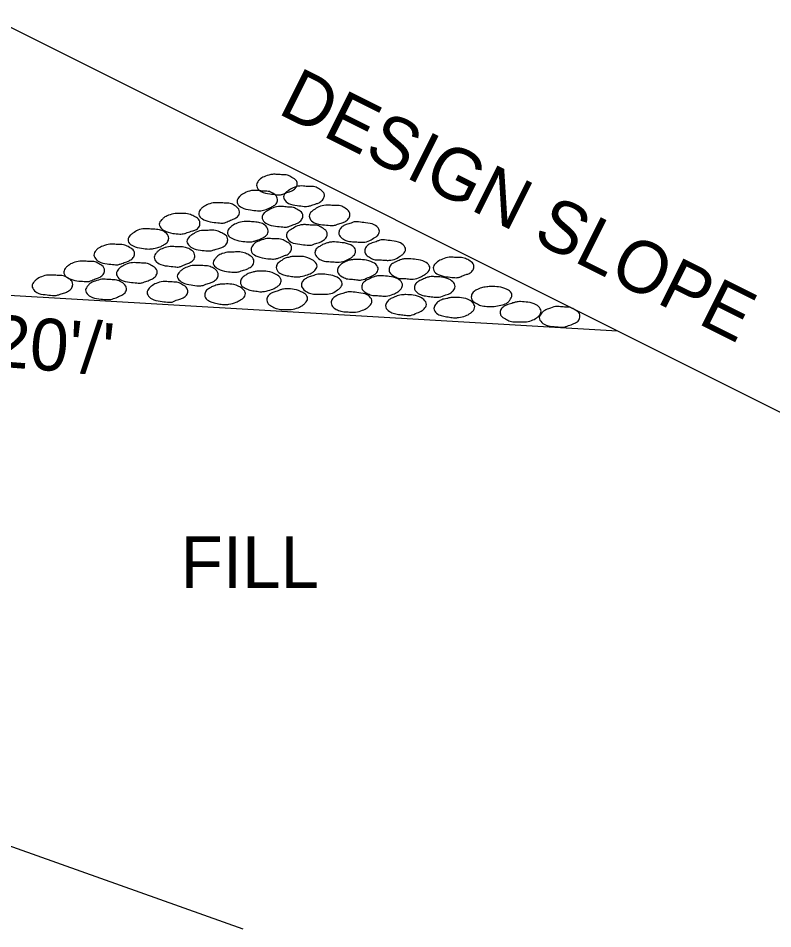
# Model space of a CAD drawing. Extents: x 634177 to 635904, y 289936 to 290970.
# Drawn here: x 635744.28 to 635753.03, y 290602.44 to 290612.98 of the extents above; entities that cross this region are included whole.
import ezdxf

# ---------------------------------------------------------------- set-up
doc = ezdxf.new("R2010")
doc.units = 0
doc.layers.add('R_Draft', color=7, linetype='Continuous')

msp = doc.modelspace()

# ---------------------------------------------------------------- linework, layer by layer
at = {"layer": 'R_Draft'}
for p, q in [((635756.401, 290606.774), (635743.982, 290612.982)), ((635735.846, 290610.262), (635751.226, 290609.361)), ((635729.503, 290608.624), (635746.886, 290602.438))]:
    msp.add_line(p, q, dxfattribs=at)
for points in [[(635747.281, 290610.938), (635747.198, 290610.949), (635747.101, 290610.974), (635747.053, 290611.023), (635747.046, 290611.049), (635747.07, 290611.101), (635747.093, 290611.123), (635747.151, 290611.153), (635747.23, 290611.174), (635747.272, 290611.174), (635747.335, 290611.17), (635747.404, 290611.165), (635747.456, 290611.139), (635747.509, 290611.098), (635747.517, 290611.062), (635747.503, 290611.02), (635747.464, 290610.988), (635747.426, 290610.973), (635747.369, 290610.953), (635747.335, 290610.94), (635747.281, 290610.938)], [(635747.057, 290610.752), (635746.974, 290610.762), (635746.874, 290610.789), (635746.826, 290610.835), (635746.82, 290610.864), (635746.845, 290610.912), (635746.872, 290610.937), (635746.927, 290610.968), (635747.006, 290610.988), (635747.049, 290610.988), (635747.11, 290610.981), (635747.181, 290610.977), (635747.233, 290610.957), (635747.281, 290610.91), (635747.289, 290610.882), (635747.274, 290610.833), (635747.237, 290610.806), (635747.2, 290610.785), (635747.143, 290610.763), (635747.11, 290610.754), (635747.057, 290610.752)], [(635747.598, 290610.803), (635747.517, 290610.814), (635747.416, 290610.837), (635747.367, 290610.886), (635747.36, 290610.912), (635747.386, 290610.965), (635747.414, 290610.985), (635747.469, 290611.017), (635747.548, 290611.039), (635747.588, 290611.039), (635747.653, 290611.032), (635747.722, 290611.029), (635747.776, 290611.002), (635747.824, 290610.961), (635747.833, 290610.926), (635747.816, 290610.886), (635747.781, 290610.851), (635747.74, 290610.835), (635747.686, 290610.816), (635747.653, 290610.806), (635747.598, 290610.803)], [(635746.618, 290610.611), (635746.533, 290610.62), (635746.434, 290610.649), (635746.383, 290610.693), (635746.378, 290610.725), (635746.403, 290610.774), (635746.431, 290610.798), (635746.485, 290610.827), (635746.566, 290610.845), (635746.608, 290610.845), (635746.671, 290610.842), (635746.741, 290610.838), (635746.792, 290610.815), (635746.84, 290610.77), (635746.848, 290610.74), (635746.832, 290610.692), (635746.794, 290610.663), (635746.758, 290610.648), (635746.704, 290610.624), (635746.671, 290610.611), (635746.618, 290610.611)], [(635747.352, 290610.565), (635747.266, 290610.574), (635747.168, 290610.6), (635747.117, 290610.649), (635747.11, 290610.675), (635747.135, 290610.728), (635747.164, 290610.749), (635747.219, 290610.779), (635747.299, 290610.802), (635747.342, 290610.802), (635747.404, 290610.795), (635747.473, 290610.792), (635747.524, 290610.763), (635747.575, 290610.725), (635747.583, 290610.688), (635747.566, 290610.646), (635747.528, 290610.612), (635747.492, 290610.599), (635747.438, 290610.578), (635747.404, 290610.566), (635747.352, 290610.565)], [(635747.899, 290610.582), (635747.811, 290610.591), (635747.715, 290610.613), (635747.662, 290610.665), (635747.656, 290610.69), (635747.682, 290610.742), (635747.711, 290610.763), (635747.767, 290610.797), (635747.847, 290610.817), (635747.887, 290610.817), (635747.951, 290610.814), (635748.019, 290610.809), (635748.073, 290610.781), (635748.119, 290610.741), (635748.128, 290610.707), (635748.112, 290610.662), (635748.076, 290610.63), (635748.038, 290610.612), (635747.984, 290610.596), (635747.951, 290610.584), (635747.899, 290610.582)], [(635746.157, 290610.482), (635746.075, 290610.491), (635745.975, 290610.525), (635745.928, 290610.566), (635745.919, 290610.596), (635745.945, 290610.646), (635745.973, 290610.672), (635746.026, 290610.7), (635746.104, 290610.719), (635746.149, 290610.719), (635746.21, 290610.722), (635746.279, 290610.708), (635746.335, 290610.683), (635746.383, 290610.642), (635746.39, 290610.611), (635746.378, 290610.564), (635746.339, 290610.531), (635746.303, 290610.519), (635746.243, 290610.5), (635746.21, 290610.488), (635746.157, 290610.482)], [(635745.8, 290610.309), (635745.714, 290610.318), (635745.616, 290610.345), (635745.564, 290610.389), (635745.558, 290610.419), (635745.582, 290610.468), (635745.614, 290610.493), (635745.671, 290610.527), (635745.75, 290610.543), (635745.789, 290610.543), (635745.851, 290610.539), (635745.921, 290610.532), (635745.974, 290610.512), (635746.022, 290610.464), (635746.028, 290610.437), (635746.013, 290610.388), (635745.975, 290610.36), (635745.941, 290610.34), (635745.888, 290610.323), (635745.854, 290610.315), (635745.8, 290610.309)], [(635746.952, 290610.391), (635746.867, 290610.401), (635746.766, 290610.43), (635746.714, 290610.474), (635746.708, 290610.505), (635746.736, 290610.553), (635746.762, 290610.578), (635746.823, 290610.609), (635746.901, 290610.628), (635746.94, 290610.628), (635747.003, 290610.624), (635747.071, 290610.616), (635747.127, 290610.597), (635747.173, 290610.549), (635747.181, 290610.522), (635747.165, 290610.472), (635747.129, 290610.446), (635747.092, 290610.426), (635747.04, 290610.408), (635747.006, 290610.397), (635746.952, 290610.391)], [(635747.631, 290610.353), (635747.547, 290610.365), (635747.448, 290610.388), (635747.4, 290610.438), (635747.392, 290610.463), (635747.417, 290610.518), (635747.446, 290610.536), (635747.503, 290610.569), (635747.581, 290610.591), (635747.622, 290610.591), (635747.684, 290610.585), (635747.754, 290610.581), (635747.806, 290610.555), (635747.857, 290610.514), (635747.864, 290610.479), (635747.85, 290610.437), (635747.81, 290610.404), (635747.774, 290610.386), (635747.718, 290610.37), (635747.684, 290610.356), (635747.631, 290610.353)], [(635748.228, 290610.624), (635748.31, 290610.613), (635748.409, 290610.591), (635748.463, 290610.541), (635748.469, 290610.517), (635748.446, 290610.463), (635748.416, 290610.443), (635748.357, 290610.407), (635748.279, 290610.388), (635748.238, 290610.388), (635748.177, 290610.394), (635748.105, 290610.399), (635748.053, 290610.423), (635748.006, 290610.466), (635748, 290610.5), (635748.015, 290610.543), (635748.048, 290610.576), (635748.086, 290610.594), (635748.141, 290610.609), (635748.175, 290610.623), (635748.228, 290610.624)], [(635746.479, 290610.287), (635746.396, 290610.297), (635746.3, 290610.323), (635746.249, 290610.371), (635746.24, 290610.395), (635746.267, 290610.451), (635746.297, 290610.474), (635746.347, 290610.506), (635746.428, 290610.525), (635746.47, 290610.525), (635746.533, 290610.527), (635746.603, 290610.515), (635746.656, 290610.488), (635746.706, 290610.448), (635746.712, 290610.416), (635746.699, 290610.37), (635746.661, 290610.336), (635746.622, 290610.319), (635746.566, 290610.304), (635746.533, 290610.293), (635746.479, 290610.287)], [(635747.217, 290610.194), (635747.134, 290610.203), (635747.037, 290610.232), (635746.987, 290610.277), (635746.982, 290610.307), (635747.006, 290610.357), (635747.029, 290610.38), (635747.088, 290610.408), (635747.166, 290610.43), (635747.207, 290610.43), (635747.27, 290610.426), (635747.34, 290610.421), (635747.393, 290610.394), (635747.445, 290610.353), (635747.451, 290610.319), (635747.437, 290610.274), (635747.4, 290610.244), (635747.362, 290610.23), (635747.305, 290610.207), (635747.27, 290610.196), (635747.217, 290610.194)], [(635745.398, 290610.129), (635745.314, 290610.138), (635745.218, 290610.165), (635745.171, 290610.213), (635745.162, 290610.24), (635745.186, 290610.293), (635745.209, 290610.315), (635745.266, 290610.343), (635745.347, 290610.366), (635745.388, 290610.366), (635745.45, 290610.362), (635745.52, 290610.356), (635745.573, 290610.329), (635745.625, 290610.289), (635745.632, 290610.254), (635745.618, 290610.21), (635745.578, 290610.179), (635745.543, 290610.163), (635745.485, 290610.142), (635745.45, 290610.13), (635745.398, 290610.129)], [(635746.099, 290610.103), (635746.013, 290610.113), (635745.916, 290610.139), (635745.868, 290610.186), (635745.861, 290610.215), (635745.886, 290610.265), (635745.91, 290610.29), (635745.968, 290610.319), (635746.047, 290610.337), (635746.088, 290610.337), (635746.152, 290610.335), (635746.221, 290610.329), (635746.273, 290610.307), (635746.324, 290610.261), (635746.331, 290610.232), (635746.315, 290610.183), (635746.279, 290610.156), (635746.24, 290610.138), (635746.184, 290610.116), (635746.152, 290610.103), (635746.099, 290610.103)], [(635747.951, 290610.392), (635748.038, 290610.383), (635748.137, 290610.357), (635748.188, 290610.31), (635748.194, 290610.281), (635748.17, 290610.233), (635748.141, 290610.209), (635748.082, 290610.177), (635748.005, 290610.158), (635747.962, 290610.158), (635747.901, 290610.163), (635747.831, 290610.167), (635747.779, 290610.19), (635747.731, 290610.235), (635747.723, 290610.265), (635747.738, 290610.311), (635747.778, 290610.34), (635747.811, 290610.36), (635747.867, 290610.38), (635747.901, 290610.389), (635747.951, 290610.392)], [(635748.529, 290610.414), (635748.614, 290610.405), (635748.713, 290610.38), (635748.765, 290610.331), (635748.772, 290610.306), (635748.746, 290610.252), (635748.718, 290610.232), (635748.659, 290610.197), (635748.583, 290610.179), (635748.539, 290610.179), (635748.476, 290610.183), (635748.404, 290610.188), (635748.355, 290610.214), (635748.307, 290610.255), (635748.3, 290610.29), (635748.316, 290610.333), (635748.351, 290610.366), (635748.387, 290610.381), (635748.444, 290610.399), (635748.475, 290610.412), (635748.529, 290610.414)], [(635746.782, 290610.04), (635746.699, 290610.049), (635746.601, 290610.079), (635746.551, 290610.123), (635746.543, 290610.151), (635746.569, 290610.201), (635746.598, 290610.23), (635746.649, 290610.256), (635746.73, 290610.274), (635746.771, 290610.274), (635746.833, 290610.277), (635746.903, 290610.265), (635746.957, 290610.241), (635747.008, 290610.197), (635747.015, 290610.169), (635747, 290610.12), (635746.962, 290610.091), (635746.924, 290610.074), (635746.868, 290610.057), (635746.833, 290610.044), (635746.782, 290610.04)], [(635747.507, 290610.223), (635747.588, 290610.221), (635747.692, 290610.184), (635747.739, 290610.139), (635747.747, 290610.11), (635747.72, 290610.061), (635747.693, 290610.037), (635747.638, 290610.012), (635747.557, 290609.99), (635747.515, 290609.987), (635747.452, 290609.993), (635747.386, 290610.004), (635747.332, 290610.022), (635747.283, 290610.064), (635747.275, 290610.094), (635747.29, 290610.141), (635747.329, 290610.171), (635747.364, 290610.196), (635747.418, 290610.213), (635747.453, 290610.221), (635747.507, 290610.223)], [(635745.05, 290609.935), (635744.965, 290609.941), (635744.871, 290609.969), (635744.82, 290610.015), (635744.813, 290610.044), (635744.839, 290610.095), (635744.866, 290610.119), (635744.921, 290610.15), (635744.998, 290610.169), (635745.04, 290610.169), (635745.106, 290610.166), (635745.176, 290610.162), (635745.226, 290610.136), (635745.277, 290610.093), (635745.285, 290610.061), (635745.269, 290610.015), (635745.234, 290609.985), (635745.192, 290609.968), (635745.136, 290609.945), (635745.106, 290609.935), (635745.05, 290609.935)], [(635745.659, 290609.917), (635745.574, 290609.925), (635745.48, 290609.949), (635745.43, 290609.998), (635745.422, 290610.025), (635745.448, 290610.078), (635745.472, 290610.099), (635745.529, 290610.13), (635745.61, 290610.151), (635745.648, 290610.151), (635745.713, 290610.147), (635745.781, 290610.142), (635745.835, 290610.116), (635745.886, 290610.074), (635745.895, 290610.041), (635745.878, 290609.996), (635745.84, 290609.965), (635745.803, 290609.947), (635745.749, 290609.93), (635745.713, 290609.917), (635745.659, 290609.917)], [(635746.375, 290609.883), (635746.288, 290609.893), (635746.188, 290609.922), (635746.137, 290609.966), (635746.128, 290609.996), (635746.156, 290610.046), (635746.184, 290610.07), (635746.242, 290610.101), (635746.32, 290610.12), (635746.362, 290610.12), (635746.424, 290610.117), (635746.494, 290610.11), (635746.547, 290610.088), (635746.594, 290610.042), (635746.603, 290610.012), (635746.586, 290609.965), (635746.548, 290609.935), (635746.512, 290609.918), (635746.46, 290609.902), (635746.426, 290609.889), (635746.375, 290609.883)], [(635748.21, 290610.189), (635748.295, 290610.183), (635748.395, 290610.154), (635748.449, 290610.105), (635748.455, 290610.078), (635748.428, 290610.026), (635748.399, 290610.006), (635748.34, 290609.979), (635748.26, 290609.951), (635748.218, 290609.951), (635748.156, 290609.959), (635748.088, 290609.966), (635748.037, 290609.989), (635747.99, 290610.03), (635747.982, 290610.062), (635747.998, 290610.107), (635748.031, 290610.138), (635748.066, 290610.158), (635748.121, 290610.179), (635748.157, 290610.186), (635748.21, 290610.189)], [(635748.814, 290610.197), (635748.897, 290610.188), (635748.995, 290610.163), (635749.047, 290610.116), (635749.054, 290610.088), (635749.025, 290610.036), (635748.997, 290610.015), (635748.942, 290609.984), (635748.862, 290609.961), (635748.821, 290609.961), (635748.759, 290609.968), (635748.69, 290609.972), (635748.637, 290609.996), (635748.588, 290610.04), (635748.583, 290610.071), (635748.594, 290610.116), (635748.633, 290610.147), (635748.669, 290610.165), (635748.725, 290610.188), (635748.762, 290610.196), (635748.814, 290610.197)], [(635749.33, 290609.979), (635749.246, 290609.989), (635749.149, 290610.015), (635749.1, 290610.061), (635749.092, 290610.09), (635749.119, 290610.141), (635749.144, 290610.163), (635749.2, 290610.192), (635749.277, 290610.214), (635749.322, 290610.214), (635749.384, 290610.21), (635749.453, 290610.205), (635749.505, 290610.179), (635749.556, 290610.137), (635749.563, 290610.103), (635749.549, 290610.059), (635749.512, 290610.027), (635749.474, 290610.014), (635749.415, 290609.992), (635749.384, 290609.98), (635749.33, 290609.979)], [(635747.091, 290610.053), (635747.174, 290610.05), (635747.274, 290610.015), (635747.324, 290609.969), (635747.331, 290609.939), (635747.305, 290609.889), (635747.275, 290609.866), (635747.221, 290609.841), (635747.138, 290609.819), (635747.098, 290609.815), (635747.037, 290609.822), (635746.969, 290609.834), (635746.915, 290609.855), (635746.867, 290609.893), (635746.859, 290609.926), (635746.874, 290609.971), (635746.912, 290610.001), (635746.947, 290610.025), (635747.003, 290610.042), (635747.038, 290610.05), (635747.091, 290610.053)], [(635747.795, 290610.019), (635747.879, 290610.012), (635747.979, 290609.982), (635748.03, 290609.937), (635748.038, 290609.91), (635748.012, 290609.858), (635747.984, 290609.836), (635747.926, 290609.799), (635747.85, 290609.786), (635747.806, 290609.786), (635747.742, 290609.787), (635747.674, 290609.794), (635747.622, 290609.818), (635747.575, 290609.862), (635747.566, 290609.893), (635747.583, 290609.938), (635747.62, 290609.969), (635747.656, 290609.987), (635747.71, 290610.004), (635747.741, 290610.015), (635747.795, 290610.019)], [(635744.681, 290609.773), (635744.598, 290609.781), (635744.502, 290609.805), (635744.454, 290609.855), (635744.445, 290609.881), (635744.473, 290609.935), (635744.496, 290609.956), (635744.553, 290609.989), (635744.633, 290610.008), (635744.672, 290610.008), (635744.737, 290610.004), (635744.807, 290609.998), (635744.862, 290609.973), (635744.909, 290609.932), (635744.917, 290609.898), (635744.901, 290609.854), (635744.867, 290609.822), (635744.824, 290609.803), (635744.77, 290609.786), (635744.737, 290609.775), (635744.681, 290609.773)], [(635745.306, 290609.724), (635745.219, 290609.732), (635745.121, 290609.76), (635745.073, 290609.805), (635745.065, 290609.836), (635745.095, 290609.886), (635745.115, 290609.91), (635745.176, 290609.938), (635745.253, 290609.959), (635745.294, 290609.959), (635745.357, 290609.955), (635745.426, 290609.949), (635745.48, 290609.926), (635745.531, 290609.881), (635745.539, 290609.851), (635745.522, 290609.803), (635745.485, 290609.776), (635745.448, 290609.758), (635745.39, 290609.735), (635745.357, 290609.726), (635745.306, 290609.724)], [(635746.014, 290609.695), (635745.93, 290609.705), (635745.834, 290609.731), (635745.785, 290609.779), (635745.778, 290609.803), (635745.803, 290609.858), (635745.828, 290609.879), (635745.884, 290609.912), (635745.963, 290609.932), (635746.005, 290609.932), (635746.069, 290609.928), (635746.137, 290609.922), (635746.19, 290609.896), (635746.24, 290609.855), (635746.249, 290609.82), (635746.235, 290609.777), (635746.195, 290609.744), (635746.159, 290609.73), (635746.101, 290609.71), (635746.069, 290609.696), (635746.014, 290609.695)], [(635746.678, 290609.904), (635746.758, 290609.902), (635746.859, 290609.866), (635746.909, 290609.82), (635746.917, 290609.793), (635746.892, 290609.74), (635746.86, 290609.72), (635746.809, 290609.693), (635746.725, 290609.67), (635746.684, 290609.667), (635746.622, 290609.672), (635746.555, 290609.685), (635746.502, 290609.706), (635746.453, 290609.744), (635746.446, 290609.778), (635746.46, 290609.822), (635746.498, 290609.854), (635746.534, 290609.875), (635746.589, 290609.893), (635746.624, 290609.902), (635746.678, 290609.904)], [(635748.497, 290609.999), (635748.583, 290609.992), (635748.681, 290609.964), (635748.73, 290609.917), (635748.737, 290609.888), (635748.713, 290609.839), (635748.683, 290609.813), (635748.628, 290609.786), (635748.548, 290609.765), (635748.509, 290609.765), (635748.446, 290609.77), (635748.376, 290609.775), (635748.323, 290609.799), (635748.271, 290609.841), (635748.265, 290609.871), (635748.281, 290609.919), (635748.32, 290609.947), (635748.356, 290609.965), (635748.409, 290609.989), (635748.446, 290609.998), (635748.497, 290609.999)], [(635749.108, 290609.989), (635749.19, 290609.984), (635749.292, 290609.951), (635749.339, 290609.905), (635749.346, 290609.875), (635749.322, 290609.825), (635749.297, 290609.801), (635749.239, 290609.778), (635749.161, 290609.752), (635749.119, 290609.752), (635749.054, 290609.758), (635748.988, 290609.769), (635748.933, 290609.788), (635748.884, 290609.83), (635748.874, 290609.864), (635748.892, 290609.909), (635748.928, 290609.938), (635748.968, 290609.958), (635749.02, 290609.98), (635749.054, 290609.989), (635749.108, 290609.989)], [(635747.4, 290609.85), (635747.482, 290609.841), (635747.581, 290609.807), (635747.63, 290609.765), (635747.638, 290609.735), (635747.611, 290609.687), (635747.583, 290609.66), (635747.528, 290609.63), (635747.448, 290609.611), (635747.407, 290609.611), (635747.345, 290609.61), (635747.275, 290609.621), (635747.221, 290609.646), (635747.173, 290609.689), (635747.165, 290609.718), (635747.181, 290609.767), (635747.217, 290609.797), (635747.256, 290609.813), (635747.312, 290609.832), (635747.345, 290609.843), (635747.4, 290609.85)], [(635748.145, 290609.813), (635748.23, 290609.803), (635748.328, 290609.779), (635748.376, 290609.731), (635748.383, 290609.703), (635748.356, 290609.653), (635748.331, 290609.63), (635748.273, 290609.6), (635748.194, 290609.578), (635748.154, 290609.578), (635748.093, 290609.582), (635748.023, 290609.589), (635747.969, 290609.611), (635747.918, 290609.656), (635747.911, 290609.687), (635747.926, 290609.732), (635747.964, 290609.764), (635748.002, 290609.781), (635748.058, 290609.799), (635748.093, 290609.81), (635748.145, 290609.813)], [(635749.766, 290609.877), (635749.85, 290609.871), (635749.948, 290609.841), (635749.999, 290609.799), (635750.005, 290609.773), (635749.979, 290609.718), (635749.954, 290609.689), (635749.894, 290609.664), (635749.817, 290609.647), (635749.777, 290609.645), (635749.714, 290609.645), (635749.642, 290609.656), (635749.593, 290609.68), (635749.542, 290609.72), (635749.534, 290609.752), (635749.548, 290609.799), (635749.587, 290609.833), (635749.623, 290609.85), (635749.68, 290609.866), (635749.713, 290609.871), (635749.766, 290609.877)], [(635748.776, 290609.781), (635748.862, 290609.776), (635748.958, 290609.743), (635749.006, 290609.697), (635749.014, 290609.667), (635748.988, 290609.617), (635748.965, 290609.596), (635748.908, 290609.57), (635748.829, 290609.541), (635748.787, 290609.541), (635748.725, 290609.549), (635748.658, 290609.558), (635748.601, 290609.578), (635748.549, 290609.621), (635748.541, 290609.654), (635748.558, 290609.698), (635748.594, 290609.73), (635748.633, 290609.749), (635748.69, 290609.772), (635748.725, 290609.779), (635748.776, 290609.781)], [(635749.337, 290609.748), (635749.419, 290609.745), (635749.519, 290609.714), (635749.564, 290609.668), (635749.573, 290609.643), (635749.548, 290609.587), (635749.523, 290609.566), (635749.468, 290609.536), (635749.387, 290609.517), (635749.342, 290609.512), (635749.282, 290609.52), (635749.214, 290609.532), (635749.159, 290609.549), (635749.11, 290609.591), (635749.101, 290609.621), (635749.119, 290609.667), (635749.153, 290609.701), (635749.191, 290609.723), (635749.249, 290609.736), (635749.284, 290609.745), (635749.337, 290609.748)], [(635750.105, 290609.701), (635750.189, 290609.693), (635750.286, 290609.663), (635750.333, 290609.617), (635750.342, 290609.591), (635750.318, 290609.536), (635750.291, 290609.512), (635750.233, 290609.482), (635750.154, 290609.466), (635750.113, 290609.466), (635750.05, 290609.468), (635749.983, 290609.473), (635749.929, 290609.5), (635749.877, 290609.54), (635749.869, 290609.575), (635749.884, 290609.619), (635749.923, 290609.652), (635749.959, 290609.667), (635750.016, 290609.685), (635750.053, 290609.696), (635750.105, 290609.701)], [(635750.561, 290609.405), (635750.474, 290609.413), (635750.377, 290609.439), (635750.329, 290609.487), (635750.322, 290609.515), (635750.35, 290609.569), (635750.371, 290609.59), (635750.43, 290609.617), (635750.51, 290609.642), (635750.551, 290609.642), (635750.613, 290609.638), (635750.682, 290609.631), (635750.735, 290609.605), (635750.786, 290609.564), (635750.791, 290609.532), (635750.779, 290609.484), (635750.742, 290609.456), (635750.705, 290609.438), (635750.646, 290609.417), (635750.613, 290609.406), (635750.561, 290609.405)]]:
    msp.add_spline(points, degree=3, dxfattribs=at)

# ---------------------------------------------------------------- texts
for s, rotation, p in [('DESIGN SLOPE', 333.435, (635747.277, 290611.886)), ("0.020'/'", 355.6232, (635742.844, 290609.039))]:
    msp.add_text(s, height=0.6, rotation=rotation, dxfattribs=at).set_placement(p)
msp.add_text('FILL', height=0.6, dxfattribs=at).set_placement((635746.165, 290606.384))

doc.saveas('drawing.dxf')
